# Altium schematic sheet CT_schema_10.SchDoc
size 741 x 377 mm
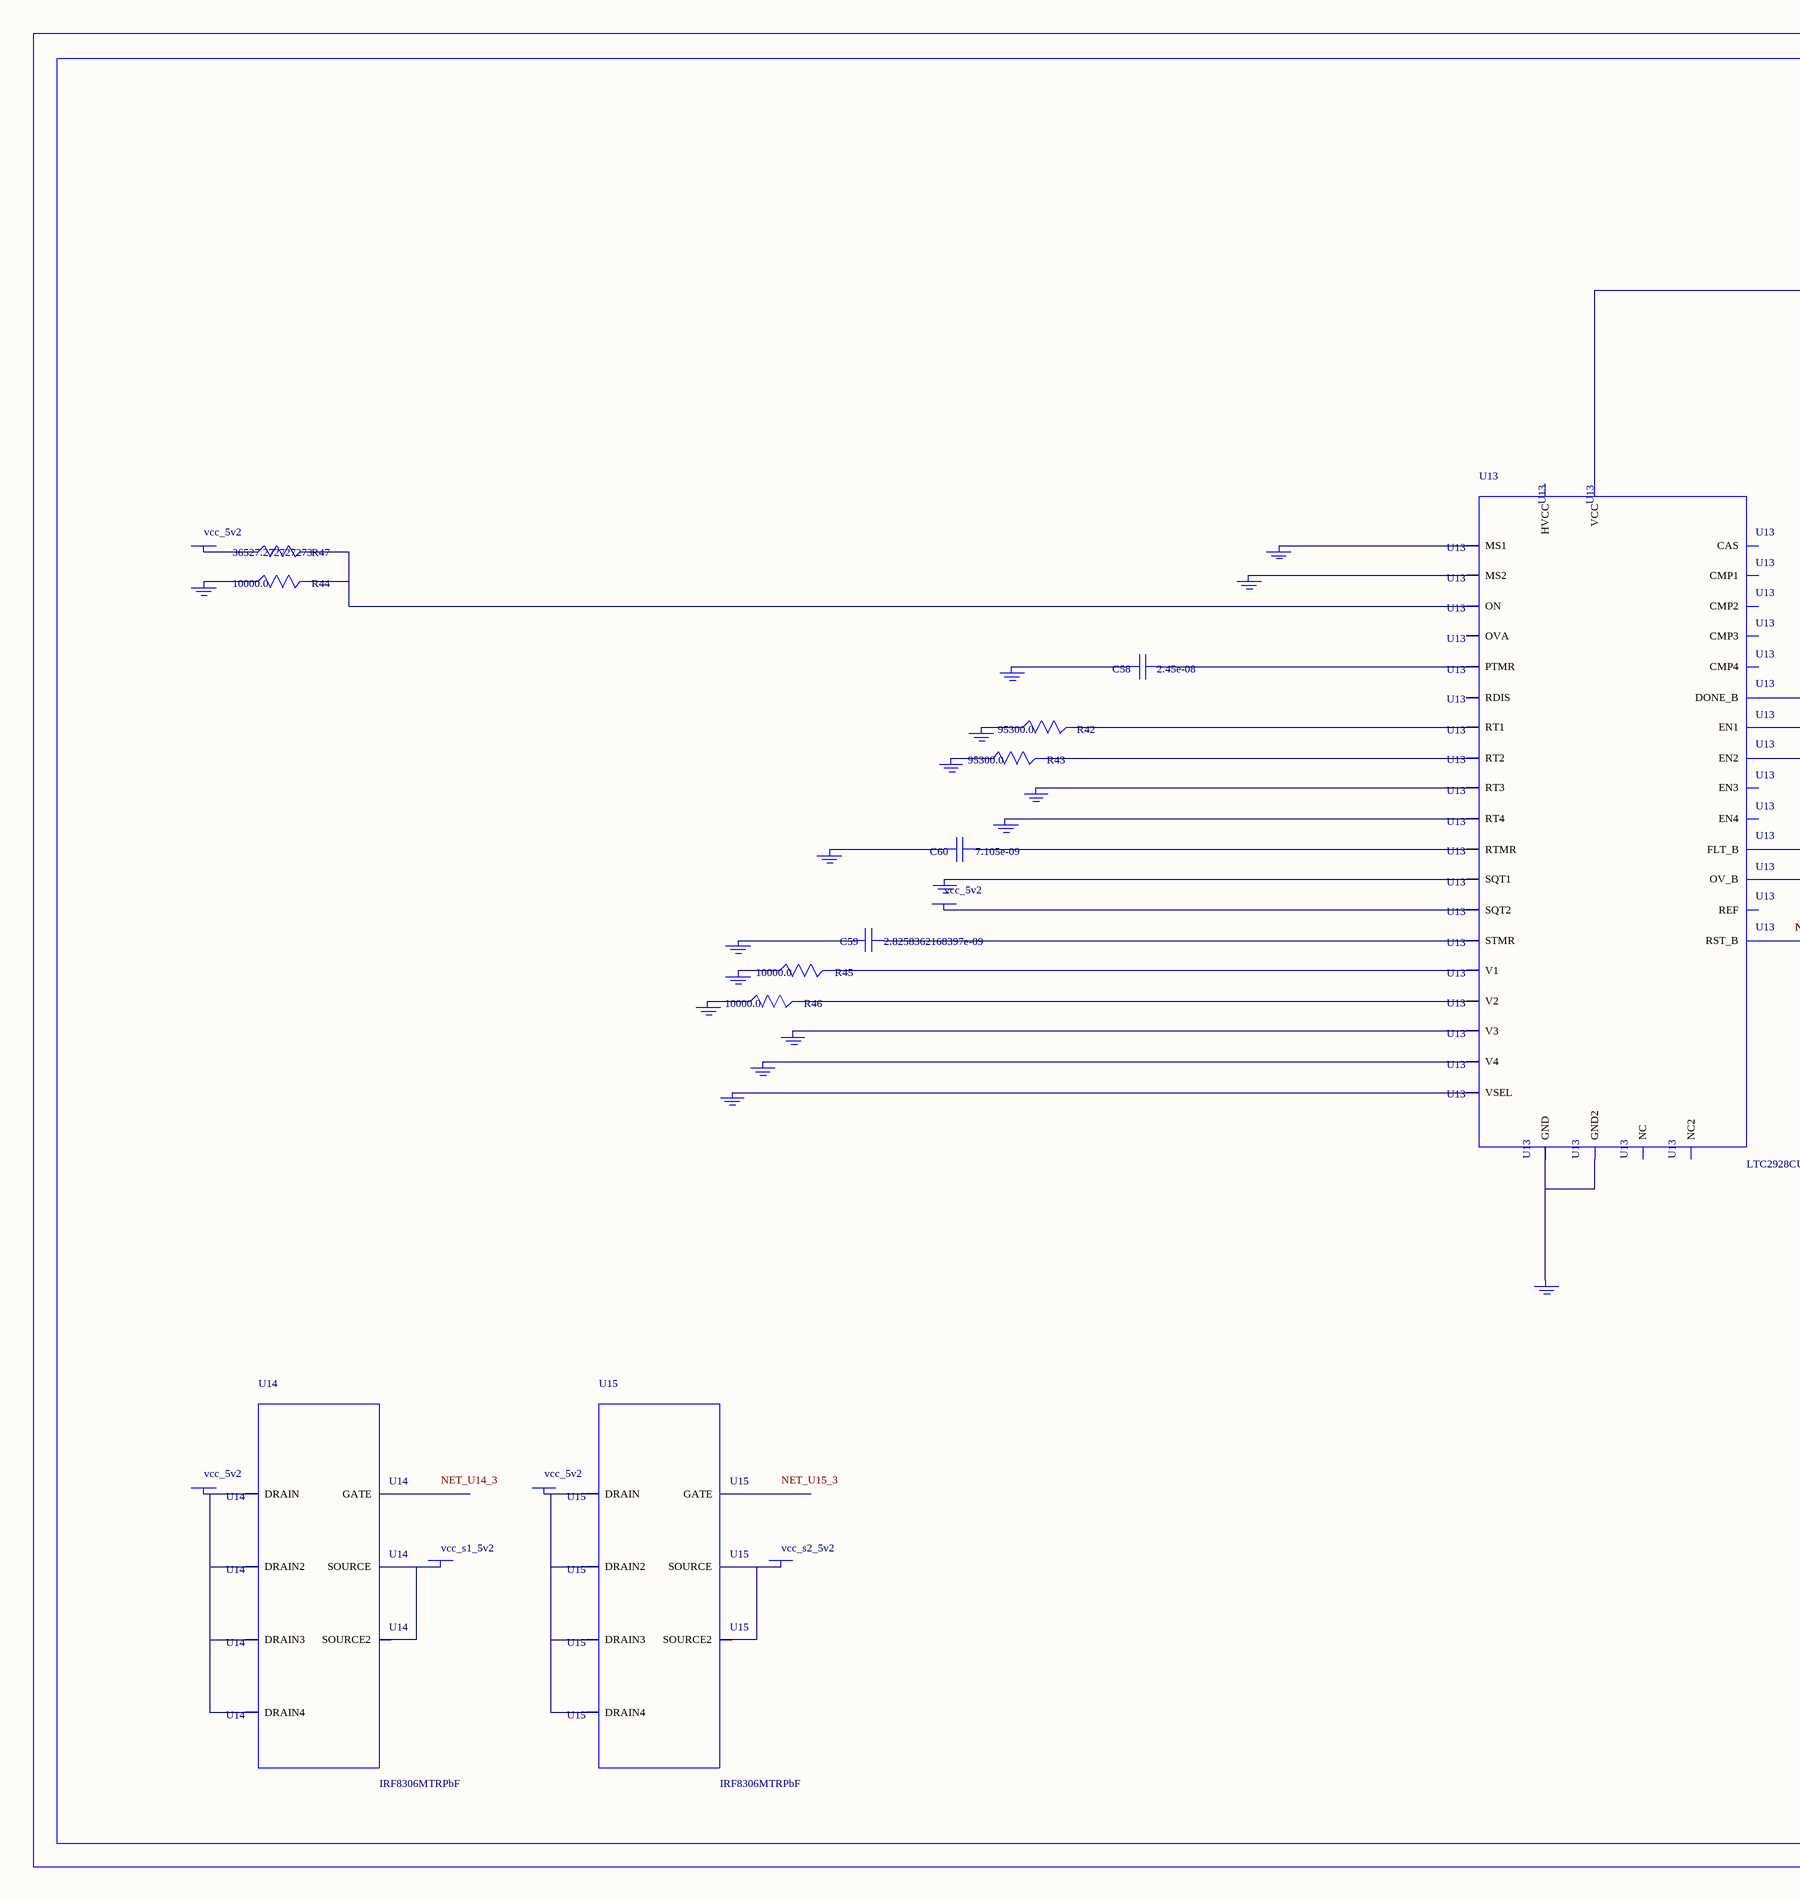
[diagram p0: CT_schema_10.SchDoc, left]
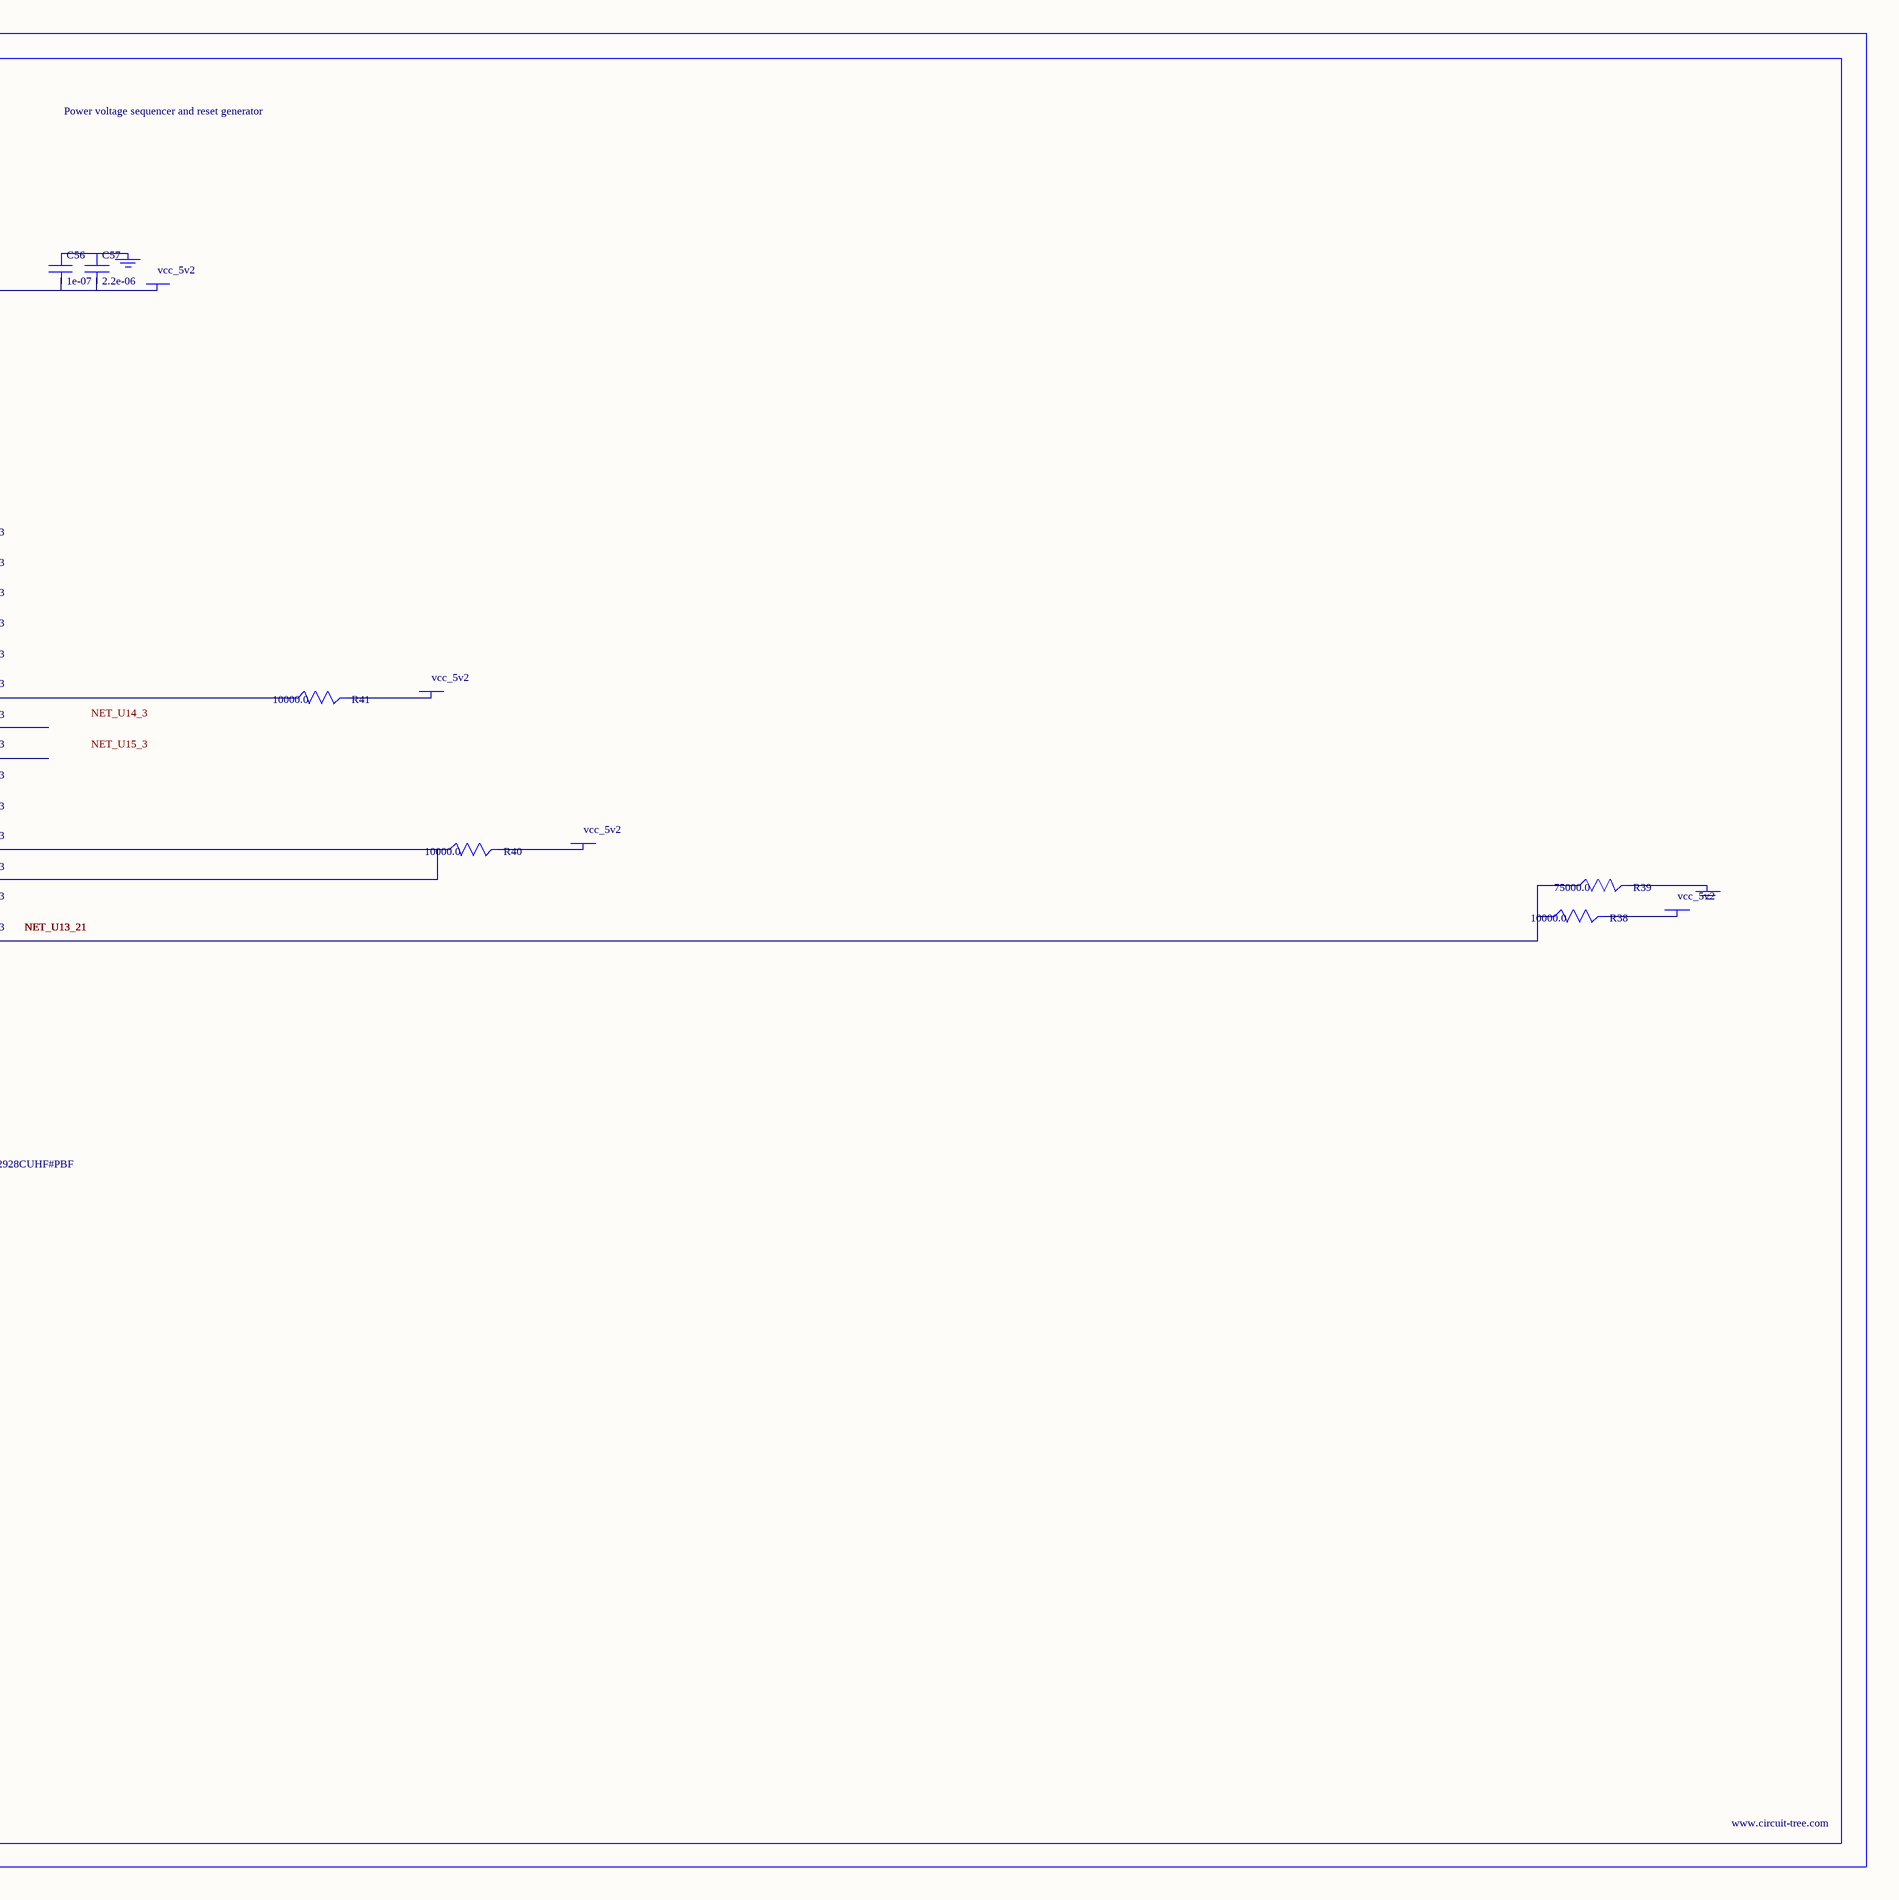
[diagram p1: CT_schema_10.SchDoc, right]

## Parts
BORDER9  (no value)
C56  1e-07  [C0402]
C57  2.2e-06  [C0603]
C58  2.45e-08  [R0603]
C59  2.8258362168397e-09  [R0603]
C60  7.105e-09  [R0603]
GND_INSTANCE_9_0  (no value)
GND_INSTANCE_9_1  (no value)
GND_INSTANCE_9_2  (no value)
GND_INSTANCE_9_3  (no value)
GND_INSTANCE_9_4  (no value)
GND_INSTANCE_9_5  (no value)
GND_INSTANCE_9_6  (no value)
GND_INSTANCE_9_7  (no value)
GND_INSTANCE_9_8  (no value)
GND_INSTANCE_9_9  (no value)
GND_INSTANCE_9_10  (no value)
GND_INSTANCE_9_11  (no value)
GND_INSTANCE_9_12  (no value)
GND_INSTANCE_9_13  (no value)
GND_INSTANCE_9_14  (no value)
GND_INSTANCE_9_15  (no value)
GND_INSTANCE_9_16  (no value)
GND_INSTANCE_9_17  (no value)
GND_INSTANCE_9_18  (no value)
POWER_INSTANCE_9_0  vcc_5v2
POWER_INSTANCE_9_1  vcc_5v2
POWER_INSTANCE_9_2  vcc_5v2
POWER_INSTANCE_9_3  vcc_5v2
POWER_INSTANCE_9_4  vcc_5v2
POWER_INSTANCE_9_5  vcc_5v2
POWER_INSTANCE_9_6  vcc_5v2
POWER_INSTANCE_9_7  vcc_s1_5v2
POWER_INSTANCE_9_8  vcc_5v2
POWER_INSTANCE_9_9  vcc_s2_5v2
R38  10000.0  [R0603]
R39  75000.0  [R0603]
R40  10000.0  [R0603]
R41  10000.0  [R0603]
R42  95300.0  [R0603]
R43  95300.0  [R0603]
R44  10000.0  [R0603]
R45  10000.0  [R0603]
R46  10000.0  [R0603]
R47  36527.272727273  [R0603]
U13  LTC2928CUHF#PBF  [QFN-38_UHF]
U14  IRF8306MTRPbF  [IRF8306MTRPBF]
U15  IRF8306MTRPbF  [IRF8306MTRPBF]

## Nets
NetC56_1: C56.1 C57.1 GND_INSTANCE_9_10.0(GND)
NetC56_2: C56.2 C57.2 POWER_INSTANCE_9_5.0(PWR) U13.22(VCC)
NetC58_1: C58.1 U13.27(PTMR)
NetC58_2: C58.2 GND_INSTANCE_9_13.0(GND)
NetC59_1: C59.1 U13.26(STMR)
NetC59_2: C59.2 GND_INSTANCE_9_12.0(GND)
NetC60_1: C60.1 U13.28(RTMR)
NetC60_2: C60.2 GND_INSTANCE_9_14.0(GND)
NetGND_INSTANCE_9_0_0: GND_INSTANCE_9_0.0(GND) R45.1
NetGND_INSTANCE_9_1_0: GND_INSTANCE_9_1.0(GND) R42.1
NetGND_INSTANCE_9_2_0: GND_INSTANCE_9_2.0(GND) R43.1
NetGND_INSTANCE_9_3_0: GND_INSTANCE_9_3.0(GND) U13.8(RT3)
NetGND_INSTANCE_9_4_0: GND_INSTANCE_9_4.0(GND) U13.9(RT4)
NetGND_INSTANCE_9_5_0: GND_INSTANCE_9_5.0(GND) U13.10(SQT1)
NetGND_INSTANCE_9_6_0: GND_INSTANCE_9_6.0(GND) U13.12(MS1)
NetGND_INSTANCE_9_7_0: GND_INSTANCE_9_7.0(GND) U13.13(MS2)
NetGND_INSTANCE_9_8_0: GND_INSTANCE_9_8.0(GND) R44.1
NetGND_INSTANCE_9_9_0: GND_INSTANCE_9_9.0(GND) R39.2
NetGND_INSTANCE_9_11_0: GND_INSTANCE_9_11.0(GND) U13.25(VSEL)
NetGND_INSTANCE_9_15_0: GND_INSTANCE_9_15.0(GND) U13.30(V4)
NetGND_INSTANCE_9_16_0: GND_INSTANCE_9_16.0(GND) U13.32(V3)
NetGND_INSTANCE_9_17_0: GND_INSTANCE_9_17.0(GND) R46.1
NetGND_INSTANCE_9_18_0: GND_INSTANCE_9_18.0(GND) U13.24(GND) U13.39(GND2)
NetPOWER_INSTANCE_9_0_0: POWER_INSTANCE_9_0.0(PWR) U13.11(SQT2)
NetPOWER_INSTANCE_9_1_0: POWER_INSTANCE_9_1.0(PWR) R47.1
NetPOWER_INSTANCE_9_2_0: POWER_INSTANCE_9_2.0(PWR) R41.2
NetPOWER_INSTANCE_9_3_0: POWER_INSTANCE_9_3.0(PWR) R40.2
NetPOWER_INSTANCE_9_4_0: POWER_INSTANCE_9_4.0(PWR) R38.2
NetPOWER_INSTANCE_9_6_0: POWER_INSTANCE_9_6.0(PWR) U14.1(DRAIN) U14.2(DRAIN2) U14.6(DRAIN3) U14.7(DRAIN4)
NetPOWER_INSTANCE_9_7_0: POWER_INSTANCE_9_7.0(PWR) U14.4(SOURCE) U14.5(SOURCE2)
NetPOWER_INSTANCE_9_8_0: POWER_INSTANCE_9_8.0(PWR) U15.1(DRAIN) U15.2(DRAIN2) U15.6(DRAIN3) U15.7(DRAIN4)
NetPOWER_INSTANCE_9_9_0: POWER_INSTANCE_9_9.0(PWR) U15.4(SOURCE) U15.5(SOURCE2)
NetR38_1: R38.1 R39.1 U13.21(RST_B)
NetR40_1: R40.1 U13.19(FLT_B) U13.20(OV_B)
NetR41_1: R41.1 U13.18(DONE_B)
NetR42_2: R42.2 U13.6(RT1)
NetR43_2: R43.2 U13.7(RT2)
NetR44_2: R44.2 R47.2 U13.16(ON)
NetR45_2: R45.2 U13.3(V1)
NetR46_2: R46.2 U13.38(V2)

Not connected (* = marked no-connect by the designer): U13 1(OVA) 2(EN1) 4(NC) 5(REF) 14(RDIS) 15(CAS) 17(NC2) 23(HVCC) 29(EN4) 31(EN3) 33(CMP3) 34(CMP4) 35(CMP1) 36(CMP2) 37(EN2); U14 3(GATE); U15 3(GATE)

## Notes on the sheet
- Labels drawn without touching a wire or pin: NET_U14_3, NET_U15_3

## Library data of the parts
BORDER9 = BORDER_PAGE9
C56 = C0402C104K3RACTU
C57 = GRM188R61H225KE1115D
C58 = C58
C59 = C59
C60 = C60
GND_INSTANCE_9_0-GND_INSTANCE_9_18 = GND
POWER_INSTANCE_9_0-POWER_INSTANCE_9_9 = PWR
R38 R40 R41 R44-R46 = RC0603JR-0710KL
R39 = RC0603JR-0775KL
R42 R43 = RC0603FR-0795K3L
R47 = R47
